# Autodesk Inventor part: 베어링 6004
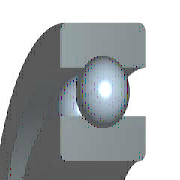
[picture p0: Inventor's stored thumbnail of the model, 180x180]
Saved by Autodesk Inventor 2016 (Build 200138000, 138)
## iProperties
Created: 2012-02
Part Number: 베어링 6004
Material: 강철, 연강
Description: 깊은 그루브 볼 베어링
Document SubType Name: Modeling
Standard: KS B 2023
Designer: mduedu
Standards Organization: KS
Language: ko-KR
Size Designation: 6004 - 20 x 42 x 12
Categories: <MemberInstance><Categories><Category DisplayName="샤프트 부품" InternalName="7f7aeb1f-a693-4053-b835-cee3144e0d98" Mnemonic="SHFT"><Category DisplayName="베어링" Inter
Density: 1 g/cm^3
Appearance: 노란색
IsCustomPart: 1
Author: mduedu
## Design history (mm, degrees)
sketch "스케치" dims "d0" = 5.72 (= -0.26 x WD + 0.26 x BD)
  geometry: L1 (3.14, 15.5)-(8.86, 15.5); L2 (6, 15.5)-(6, 12.64); L3 (6, 15.5)-(6, 18.36); L4 (3.875, 13.586)-(0, 13.586); L5 (0, 10)-(12, 10); L6 (3.875, 17.414)-(0, 17.414); L7 (0, 21)-(12, 21); L8 (12, 10)-(12, 13.586); L9 (8.125, 13.586)-(12, 13.586); L10 (8.125, 17.414)-(12, 17.414); L11 (12, 21)-(12, 17.414); L12 (-1.4, 0)-(8.4, 0) reference; L13 (0, -0.3)-(0, 5.3) reference
  constraints: 22 end point, 4 point on line, 2 collinear, 2 perpendicular, 2 symmetric about line, 1 midpoint, 1 parallel, 14 other
  dimensions: "d9" = 20 diameter of L5 L12 (= WD); "d11" = 42 diameter of L7 L12 (= BD); "d12" = 12 distance between parallel lines of L8 L13 (= KB); "d13" = 27.172 diameter of L9 L12 (= 0.326 x BD + 0.674 x WD)
revolve "본체" stored, may be unused: angle "d6" = 90 deg
revolve "볼" stored, may be unused: angle "d7" = 90 deg
pattern_circular "IDS_ARRAYBALL[SIMPL:T]" dims angle "d3" = 360 deg
body "Solid1"
fillet "모깎기1" dims "d1" = 0.6 (= KRS)
other parameters: "WD" = 20 [user parameter; used in 5 equation terms], "BD" = 42 [user parameter; used in 5 equation terms], "KB" = 12 [user parameter; used in 1 equation term], "KRS" = 0.6 [user parameter; used in 1 equation term], "d4" = 0, "d5" = 0, "d8" = 0, "d14" = 0, "d15" = 0, "BBA" = 0 [user parameter], "BC0" = 5000000 [user parameter], "BC" = 9360000 [user parameter], "BR" = 21 (= 0.5 x BD) [user parameter]
